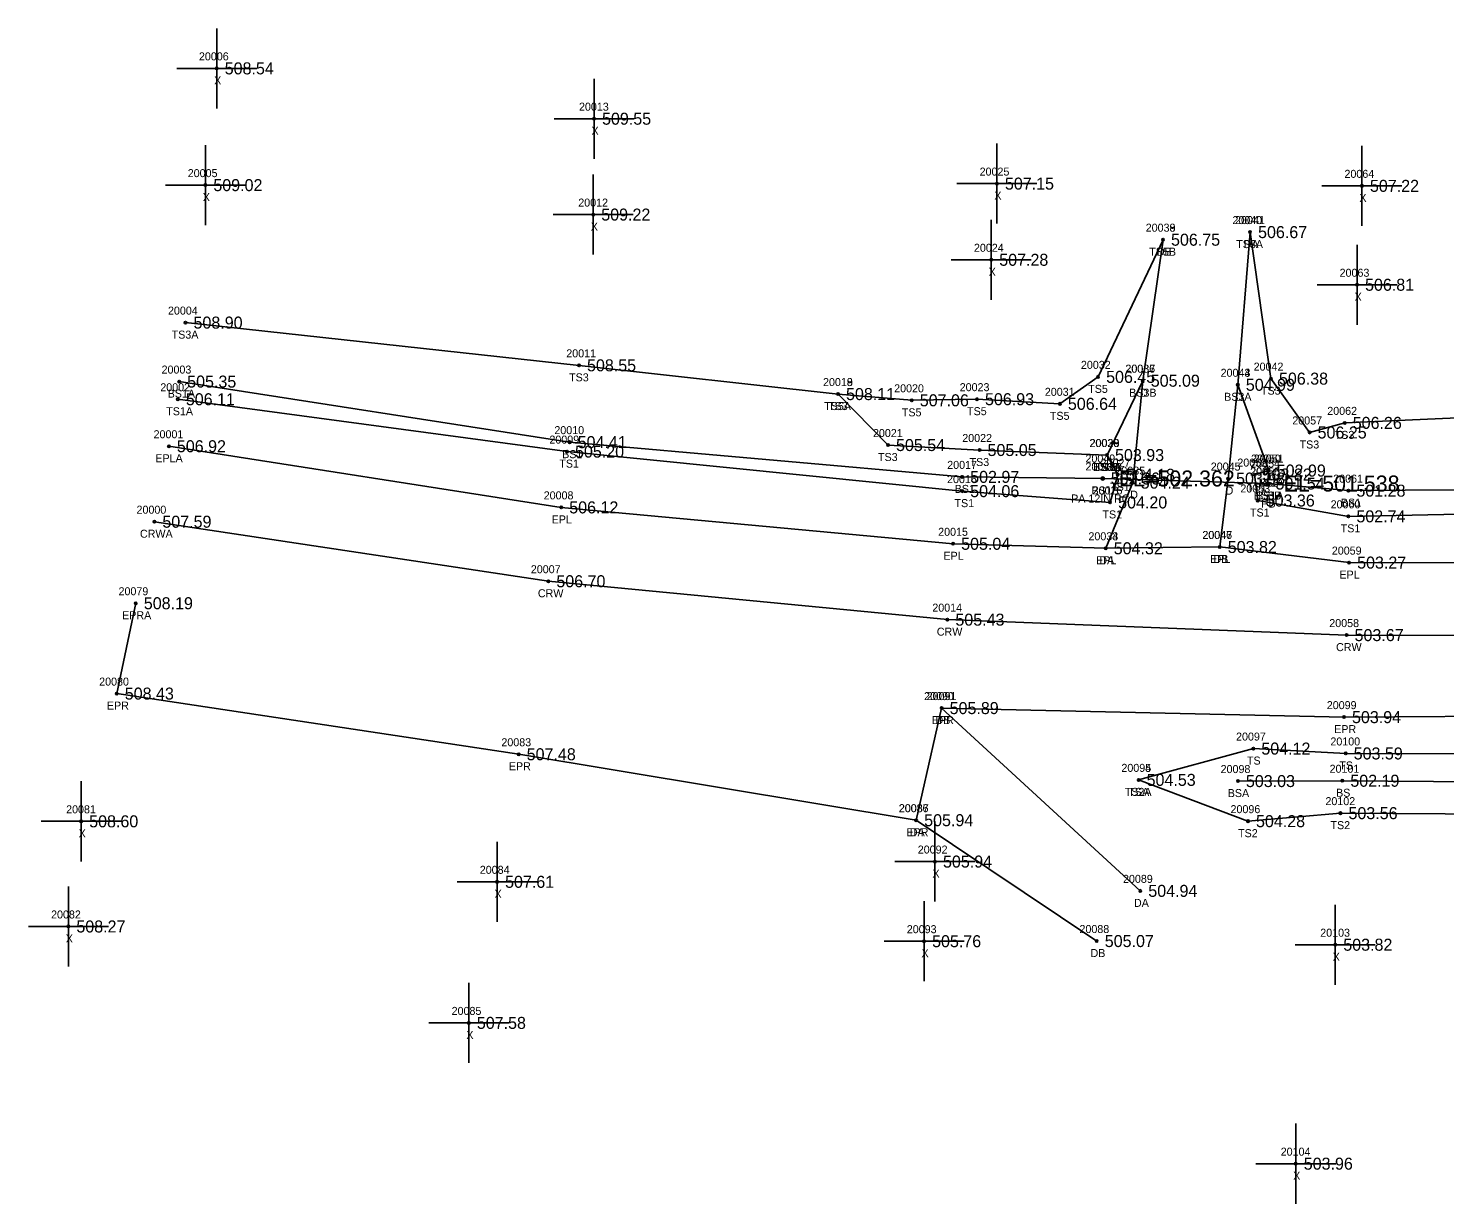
# Model space of a CAD drawing. Extents: x 1785066 to 1786589, y 770293 to 771312.
# Drawn here: x 1785066.3 to 1785243.3, y 770766.1 to 770912.9 of the extents above; entities that cross this region are included whole.
import ezdxf

# ---------------------------------------------------------------- set-up
doc = ezdxf.new("R2010")
doc.units = 0
for name, color, linetype in [('Default', 7, 'Continuous'), ('RD_DTM_BkLn1', 7, 'Continuous'), ('RD_DTM_BkLn2', 7, 'Continuous'), ('RD_DTM_BkLn_txCode', 7, 'Continuous'), ('RD_EX_DR_Pipe_txCode', 7, 'Continuous'), ('RD_EX_Driveway', 7, 'Continuous'), ('RD_EX_Driveway_txCode', 7, 'Continuous'), ('RD_EX_Misc', 7, 'Continuous'), ('RD_EX_Misc_txCode', 7, 'Continuous'), ('RD_EX_Road', 7, 'Continuous'), ('RD_EX_Road_txCode', 7, 'Continuous'), ('RD_EX_TX_Driveway_ELEV', 7, 'Continuous'), ('RD_EX_TX_Misc_ELEV', 7, 'Continuous'), ('RD_EX_TX_Road_ELEV', 7, 'Continuous'), ('RD_HC_Survey_ELEV', 7, 'Continuous'), ('RD_HC_Survey_txCode', 7, 'Continuous'), ('RD_SMD_Locator', 7, 'Continuous'), ('RD_TX_Pipe_ElevEX', 7, 'Continuous')]:
    doc.layers.add(name, color=color, linetype=linetype)

msp = doc.modelspace()

# ---------------------------------------------------------------- linework, layer by layer
at = {"layer": 'Default'}
msp.add_line((1785200.59, 770856.69), (1785221.18, 770856.06), dxfattribs=at)
at = {"layer": 'RD_DTM_BkLn1'}
msp.add_lwpolyline([(1785082.06, 770851.29), (1785131.3, 770843.85), (1785181.17, 770839.05), (1785231.06, 770837.12), (1785280.99, 770837.06), (1785330.97, 770838.45), (1785380.81, 770840.43), (1785480.56, 770843.94), (1785580.22, 770847.33), (1785679.99, 770850.66), (1785779.91, 770853.54)], dxfattribs=at)
at = {"layer": 'RD_DTM_BkLn2'}
msp.add_line((1785201.12, 770859.62), (1785205.59, 770868.91), dxfattribs=at)
for points in [[(1785219, 770887.48), (1785221.61, 770869.17), (1785226.44, 770862.44), (1785230.83, 770863.64), (1785281.61, 770865.88), (1785330.18, 770866.95), (1785380.62, 770873.53), (1785481.03, 770871.22), (1785579.17, 770869.06), (1785678.49, 770873.66), (1785753.25, 770880.69), (1785777.57, 770887.66), (1785796.72, 770894.6)], [(1785167.5, 770867.24), (1785176.72, 770866.46), (1785184.87, 770866.6), (1785195.23, 770866.02), (1785200.01, 770869.39), (1785208.12, 770886.53)], [(1785221.18, 770856.06), (1785231.29, 770855.17), (1785280.9, 770855.5), (1785330.48, 770855.32), (1785380.39, 770857.59), (1785481.4, 770861.59), (1785579.34, 770865.13), (1785679.06, 770868.59), (1785753.94, 770876.35), (1785778.96, 770883.81)], [(1785221.33, 770857.68), (1785219.57, 770857.18), (1785219.95, 770853.94), (1785231.29, 770851.96), (1785280.92, 770852.98), (1785330.39, 770854.04), (1785380.75, 770854.37), (1785480.88, 770858.51), (1785579.51, 770861.16), (1785679.28, 770865.65), (1785754.2, 770872.9), (1785779.7, 770881.19), (1785786.95, 770881.8), (1785789.14, 770878.77), (1785786.05, 770869.32), (1785786.11, 770839.44)], [(1785085.95, 770876.17), (1785135.13, 770870.83), (1785167.5, 770867.24), (1785173.75, 770860.87), (1785185.19, 770860.25), (1785201.12, 770859.62)], [(1785085.16, 770868.8), (1785133.96, 770861.23), (1785183.02, 770856.89), (1785200.59, 770856.69)], [(1785217.47, 770868.4), (1785221.33, 770857.68), (1785221.18, 770856.06)], [(1785084.99, 770866.59), (1785133.63, 770860.05), (1785183.02, 770855.11), (1785201.51, 770853.7), (1785202.47, 770857.15), (1785201.12, 770859.62)], [(1785205.07, 770819.03), (1785219.41, 770822.94), (1785230.95, 770822.33), (1785281.39, 770822.23), (1785331.37, 770822.34), (1785381.2, 770825.69), (1785481.76, 770828.75), (1785580.39, 770831.91), (1785680.81, 770834.37), (1785757.11, 770838.03), (1785775.28, 770836.8), (1785785.27, 770835.59), (1785786.11, 770839.44)], [(1785217.48, 770818.88), (1785230.53, 770818.92), (1785281.87, 770818.54), (1785331.33, 770820.31), (1785381.53, 770821.9), (1785481.77, 770825.03), (1785580.88, 770828.75), (1785679.45, 770830.28), (1785757.48, 770831.63), (1785774.02, 770829.34), (1785791.05, 770829.99), (1785795.95, 770830.77)], [(1785205.07, 770819.03), (1785218.74, 770813.87), (1785230.3, 770814.87), (1785282.58, 770814.55), (1785331.23, 770817.62), (1785381.61, 770819.76), (1785481.26, 770820.42), (1785579.63, 770825.21), (1785679.72, 770826.75), (1785756.33, 770825.6), (1785774.03, 770825.73), (1785791.3, 770827.72), (1785795.65, 770828.98)]]:
    msp.add_lwpolyline(points, dxfattribs=at)
at = {"layer": 'RD_EX_Driveway'}
for p, q in [((1785205.28, 770805.16), (1785180.45, 770828)), ((1785177.27, 770813.99), (1785199.84, 770798.89))]:
    msp.add_line(p, q, dxfattribs=at)
for points in [[(1785200.96, 770847.97), (1785204.33, 770856.17), (1785205.59, 770868.91), (1785208.12, 770886.53)], [(1785219, 770887.48), (1785217.47, 770868.4), (1785216.25, 770856.68), (1785215.21, 770848.13)]]:
    msp.add_lwpolyline(points, dxfattribs=at)
at = {"layer": 'RD_EX_Misc'}
for p, q in [((1785089.85, 770902.94), (1785089.85, 770912.94)), ((1785084.85, 770907.94), (1785094.85, 770907.94)), ((1785137.01, 770896.65), (1785137.01, 770906.65)), ((1785132.01, 770901.65), (1785142.01, 770901.65)), ((1785088.43, 770888.35), (1785088.43, 770898.35)), ((1785187.36, 770888.54), (1785187.36, 770898.54)), ((1785232.98, 770888.26), (1785232.98, 770898.26)), ((1785083.43, 770893.35), (1785093.43, 770893.35)), ((1785136.91, 770884.67), (1785136.91, 770894.67)), ((1785182.36, 770893.54), (1785192.36, 770893.54)), ((1785227.98, 770893.26), (1785237.98, 770893.26)), ((1785131.91, 770889.67), (1785141.91, 770889.67)), ((1785186.65, 770879.02), (1785186.65, 770889.02)), ((1785232.37, 770875.9), (1785232.37, 770885.9)), ((1785181.65, 770884.02), (1785191.65, 770884.02)), ((1785227.37, 770880.9), (1785237.37, 770880.9)), ((1785072.91, 770808.85), (1785072.91, 770818.85)), ((1785067.91, 770813.85), (1785077.91, 770813.85)), ((1785179.62, 770803.82), (1785179.62, 770813.82)), ((1785124.89, 770801.29), (1785124.89, 770811.29)), ((1785174.62, 770808.82), (1785184.62, 770808.82)), ((1785071.31, 770795.71), (1785071.31, 770805.71)), ((1785119.89, 770806.29), (1785129.89, 770806.29)), ((1785178.26, 770793.87), (1785178.26, 770803.87)), ((1785229.65, 770793.43), (1785229.65, 770803.43)), ((1785066.31, 770800.71), (1785076.31, 770800.71)), ((1785173.26, 770798.87), (1785183.26, 770798.87)), ((1785224.65, 770798.43), (1785234.65, 770798.43)), ((1785121.36, 770783.66), (1785121.36, 770793.66)), ((1785116.36, 770788.66), (1785126.36, 770788.66)), ((1785224.71, 770766.07), (1785224.71, 770776.07)), ((1785219.71, 770771.07), (1785229.71, 770771.07))]:
    msp.add_line(p, q, dxfattribs=at)
at = {"layer": 'RD_EX_Road'}
for points in [[(1785083.87, 770860.72), (1785132.91, 770853.08), (1785181.89, 770848.53), (1785200.96, 770847.97), (1785215.21, 770848.13), (1785231.38, 770846.18), (1785281.19, 770846.16), (1785330.68, 770847.27), (1785380.41, 770849.82), (1785480.96, 770852.71), (1785580.09, 770856.45), (1785680.2, 770859.84), (1785779.71, 770863.4)], [(1785079.74, 770841.1), (1785077.36, 770829.81), (1785127.59, 770822.23), (1785177.27, 770813.99), (1785180.45, 770828), (1785230.74, 770826.87), (1785281.16, 770827.18), (1785331.14, 770828.42), (1785381.03, 770830.27), (1785481.34, 770833.99), (1785580.1, 770837.94), (1785680.6, 770840.57), (1785780.28, 770843.87)]]:
    msp.add_lwpolyline(points, dxfattribs=at)
at = {"layer": 'RD_SMD_Locator'}
for centre, radius in [((1785089.85, 770907.94), 0.15), ((1785137.01, 770901.65), 0.15), ((1785088.43, 770893.35), 0.15), ((1785187.36, 770893.54), 0.15), ((1785232.98, 770893.26), 0.15), ((1785136.91, 770889.67), 0.15), ((1785208.12, 770886.53), 0.15), ((1785208.12, 770886.53), 0.15), ((1785219, 770887.48), 0.15), ((1785219, 770887.48), 0.15), ((1785186.65, 770884.02), 0.15), ((1785232.37, 770880.9), 0.15), ((1785085.95, 770876.17), 0.15), ((1785135.13, 770870.83), 0.15), ((1785085.16, 770868.8), 0.15), ((1785200.01, 770869.39), 0.15), ((1785205.59, 770868.91), 0.15), ((1785205.59, 770868.91), 0.15), ((1785217.47, 770868.4), 0.15), ((1785217.47, 770868.4), 0.15), ((1785221.61, 770869.17), 0.15), ((1785167.5, 770867.24), 0.15), ((1785167.5, 770867.24), 0.15), ((1785084.99, 770866.59), 0.15), ((1785176.72, 770866.46), 0.15), ((1785184.87, 770866.6), 0.15), ((1785195.23, 770866.02), 0.15), ((1785230.83, 770863.64), 0.15), ((1785226.44, 770862.44), 0.15), ((1785083.87, 770860.72), 0.15), ((1785133.63, 770860.05), 0.15), ((1785133.96, 770861.23), 0.15), ((1785173.75, 770860.87), 0.15), ((1785185.19, 770860.25), 0.15), ((1785201.12, 770859.62), 0.15), ((1785201.12, 770859.62), 0.15), ((1785201.12, 770859.62), 0.15), ((1785183.02, 770856.89), 0.15), ((1785200.59, 770856.69), 0.2), ((1785200.59, 770856.69), 0.15), ((1785202.47, 770857.15), 0.15), ((1785204.33, 770856.17), 0.15), ((1785216.25, 770856.68), 0.15), ((1785219.57, 770857.18), 0.15), ((1785221.18, 770856.06), 0.2), ((1785221.18, 770856.06), 0.15), ((1785221.18, 770856.06), 0.15), ((1785221.33, 770857.68), 0.15), ((1785221.33, 770857.68), 0.15), ((1785183.02, 770855.11), 0.15), ((1785231.29, 770855.17), 0.15), ((1785132.91, 770853.08), 0.15), ((1785201.51, 770853.7), 0.15), ((1785219.95, 770853.94), 0.15), ((1785082.06, 770851.29), 0.15), ((1785231.29, 770851.96), 0.15), ((1785181.89, 770848.53), 0.15), ((1785200.96, 770847.97), 0.15), ((1785200.96, 770847.97), 0.15), ((1785215.21, 770848.13), 0.15), ((1785215.21, 770848.13), 0.15), ((1785231.38, 770846.18), 0.15), ((1785131.3, 770843.85), 0.15), ((1785079.74, 770841.1), 0.15), ((1785181.17, 770839.05), 0.15), ((1785231.06, 770837.12), 0.15), ((1785077.36, 770829.81), 0.15), ((1785180.45, 770828), 0.15), ((1785180.45, 770828), 0.15), ((1785230.74, 770826.87), 0.15), ((1785219.41, 770822.94), 0.15), ((1785127.59, 770822.23), 0.15), ((1785230.95, 770822.33), 0.15), ((1785205.07, 770819.03), 0.15), ((1785205.07, 770819.03), 0.15), ((1785217.48, 770818.88), 0.15), ((1785230.53, 770818.92), 0.15), ((1785072.91, 770813.85), 0.15), ((1785177.27, 770813.99), 0.15), ((1785177.27, 770813.99), 0.15), ((1785218.74, 770813.87), 0.15), ((1785230.3, 770814.87), 0.15), ((1785179.62, 770808.82), 0.15), ((1785124.89, 770806.29), 0.15), ((1785205.28, 770805.16), 0.15), ((1785071.31, 770800.71), 0.15), ((1785178.26, 770798.87), 0.15), ((1785199.84, 770798.89), 0.15), ((1785229.65, 770798.43), 0.15), ((1785121.36, 770788.66), 0.15), ((1785224.71, 770771.07), 0.15)]:
    msp.add_circle(centre, radius, dxfattribs=at)

# ---------------------------------------------------------------- texts
at = {"layer": 'RD_DTM_BkLn_txCode'}
for s, p in [('20038', (1785205.96, 770887.53)), ('20041', (1785217.13, 770888.48)), ('TS3A', (1785217.27, 770885.48)), ('TS5B', (1785206.4, 770884.53)), ('20004', (1785083.76, 770877.17)), ('TS3A', (1785084.22, 770874.17)), ('20011', (1785133.54, 770871.83)), ('20003', (1785082.96, 770869.8)), ('20032', (1785197.86, 770870.39)), ('20037', (1785203.43, 770869.91)), ('20044', (1785215.32, 770869.4)), ('20042', (1785219.45, 770870.17)), ('20002', (1785082.8, 770867.59)), ('TS3', (1785133.89, 770868.83)), ('20018', (1785165.63, 770868.24)), ('20019', (1785165.63, 770868.24)), ('20023', (1785182.71, 770867.6)), ('BS1A', (1785083.72, 770866.8)), ('20020', (1785174.52, 770867.46)), ('20031', (1785193.35, 770867.02)), ('TS5', (1785198.77, 770867.39)), ('BS3B', (1785203.89, 770866.91)), ('BS3A', (1785215.76, 770866.4)), ('TS3', (1785220.36, 770867.17)), ('TS1A', (1785083.54, 770864.59)), ('TS5A', (1785165.77, 770865.24)), ('TS3', (1785166.26, 770865.24)), ('TS5', (1785175.48, 770864.46)), ('TS5', (1785183.63, 770864.6)), ('TS5', (1785193.98, 770864.02)), ('20062', (1785228.65, 770864.64)), ('20010', (1785132.05, 770862.23)), ('20057', (1785224.28, 770863.44)), ('20009', (1785131.43, 770861.05)), ('20021', (1785171.87, 770861.87)), ('20022', (1785183.03, 770861.25)), ('20030', (1785198.92, 770860.62)), ('20028', (1785198.96, 770860.62)), ('20029', (1785198.96, 770860.62)), ('TS3', (1785225.19, 770860.44)), ('TS3', (1785229.58, 770861.64)), ('BS1', (1785133.02, 770859.23)), ('TS3', (1785172.5, 770858.87)), ('20050', (1785219.13, 770858.68)), ('20051', (1785219.46, 770858.68)), ('TS1', (1785132.67, 770858.05)), ('20017', (1785181.15, 770857.89)), ('TS3', (1785183.94, 770858.25)), ('20048', (1785198.43, 770857.69)), ('TS3B', (1785199.4, 770857.62)), ('BS3A', (1785199.4, 770857.62)), ('TS1B', (1785199.68, 770857.62)), ('20027', (1785200.32, 770858.15)), ('20052', (1785217.41, 770858.18)), ('20056', (1785219, 770857.06)), ('20055', (1785219.03, 770857.06)), ('20016', (1785181.13, 770856.11)), ('TS1', (1785201.51, 770855.15)), ('TS1', (1785218.61, 770855.18)), ('TS1A', (1785219.88, 770855.68)), ('BS3', (1785220.1, 770855.68)), ('20061', (1785229.39, 770856.17)), ('BS1', (1785182.08, 770854.89)), ('BS1B', (1785199.17, 770854.69)), ('20026', (1785199.33, 770854.7)), ('20053', (1785217.79, 770854.94)), ('BS3B', (1785219.48, 770854.06)), ('BS1A', (1785219.75, 770854.06)), ('TS1', (1785182.06, 770853.11)), ('TS1', (1785200.55, 770851.7)), ('TS1', (1785218.99, 770851.94)), ('20060', (1785229.07, 770852.96)), ('BS1', (1785230.35, 770853.17)), ('TS1', (1785230.33, 770849.96)), ('20097', (1785217.25, 770823.94)), ('20100', (1785229.04, 770823.33)), ('20094', (1785202.92, 770820.03)), ('20095', (1785202.92, 770820.03)), ('20098', (1785215.32, 770819.88)), ('TS', (1785218.61, 770820.94)), ('20101', (1785228.94, 770819.92)), ('TS', (1785230.15, 770820.33)), ('TS2A', (1785203.34, 770817.03)), ('TSA', (1785203.79, 770817.03)), ('BSA', (1785216.21, 770816.88)), ('BS', (1785229.75, 770816.92)), ('20096', (1785216.56, 770814.87)), ('20102', (1785228.42, 770815.87)), ('TS2', (1785229.05, 770812.87)), ('TS2', (1785217.5, 770811.87))]:
    msp.add_text(s, height=1, dxfattribs=at).set_placement(p)
at = {"layer": 'RD_EX_DR_Pipe_txCode'}
for s, p in [('20049', (1785198.43, 770858.69)), ('20054', (1785219.03, 770858.06)), ('PA 12IN RC', (1785196.64, 770853.69)), ('PB', (1785220.4, 770853.06))]:
    msp.add_text(s, height=1, dxfattribs=at).set_placement(p)
at = {"layer": 'RD_EX_Driveway_txCode'}
for s, p in [('20039', (1785205.96, 770887.53)), ('20040', (1785216.8, 770888.48)), ('DA', (1785218.21, 770885.48)), ('DB', (1785207.34, 770884.53)), ('20036', (1785203.41, 770869.91)), ('20043', (1785215.32, 770869.4)), ('D', (1785205.28, 770866.91)), ('D', (1785217.17, 770866.4)), ('20035', (1785202.17, 770857.17)), ('20045', (1785214.09, 770857.68)), ('D', (1785204.02, 770854.17)), ('D', (1785215.94, 770854.68)), ('20034', (1785198.8, 770848.97)), ('20047', (1785213.05, 770849.13)), ('DA', (1785200.16, 770845.97)), ('DB', (1785214.43, 770846.13)), ('20090', (1785178.26, 770829)), ('DB', (1785179.68, 770826)), ('20087', (1785175.12, 770814.99)), ('DA', (1785176.48, 770811.99)), ('20089', (1785203.12, 770806.16)), ('DA', (1785204.49, 770803.16)), ('20088', (1785197.68, 770799.89)), ('DB', (1785199.06, 770796.89))]:
    msp.add_text(s, height=1, dxfattribs=at).set_placement(p)
at = {"layer": 'RD_EX_Misc_txCode'}
for s, p in [('20006', (1785087.63, 770908.94)), ('X', (1785089.53, 770905.94)), ('20013', (1785135.13, 770902.65)), ('X', (1785136.69, 770899.65)), ('20005', (1785086.23, 770894.35)), ('20025', (1785185.2, 770894.54)), ('20064', (1785230.8, 770894.26)), ('X', (1785088.11, 770891.35)), ('20012', (1785135.04, 770890.67)), ('X', (1785187.04, 770891.54)), ('X', (1785232.66, 770891.26)), ('X', (1785136.6, 770887.67)), ('20024', (1785184.49, 770885.02)), ('X', (1785186.33, 770882.02)), ('20063', (1785230.19, 770881.9)), ('X', (1785232.06, 770878.9)), ('20081', (1785071.03, 770814.85)), ('X', (1785072.59, 770811.85)), ('20092', (1785177.47, 770809.82)), ('20084', (1785122.73, 770807.29)), ('X', (1785179.31, 770806.82)), ('X', (1785124.57, 770804.29)), ('20082', (1785069.15, 770801.71)), ('X', (1785070.99, 770798.71)), ('20093', (1785176.1, 770799.87)), ('20103', (1785227.77, 770799.43)), ('X', (1785177.94, 770796.87)), ('X', (1785229.33, 770796.43)), ('20085', (1785119.21, 770789.66)), ('X', (1785121.05, 770786.66)), ('20104', (1785222.83, 770772.07)), ('X', (1785224.39, 770769.07))]:
    msp.add_text(s, height=1, dxfattribs=at).set_placement(p)
at = {"layer": 'RD_EX_Road_txCode'}
for s, p in [('20001', (1785081.96, 770861.72)), ('EPLA', (1785082.18, 770858.72)), ('20008', (1785130.72, 770854.08)), ('EPL', (1785131.71, 770851.08)), ('20015', (1785180.02, 770849.53)), ('20033', (1785198.8, 770848.97)), ('20046', (1785213.03, 770849.13)), ('EPL', (1785180.68, 770846.53)), ('20059', (1785229.22, 770847.18)), ('EPL', (1785199.75, 770845.97)), ('EPL', (1785214, 770846.13)), ('EPL', (1785230.17, 770844.18)), ('20079', (1785077.58, 770842.1)), ('EPRA', (1785078.03, 770839.1)), ('20080', (1785075.16, 770830.81)), ('20091', (1785178.58, 770829)), ('EPR', (1785076.13, 770827.81)), ('20099', (1785228.59, 770827.87)), ('EPR', (1785179.23, 770826)), ('EPR', (1785229.51, 770824.87)), ('20083', (1785125.43, 770823.23)), ('EPR', (1785126.36, 770820.23)), ('20086', (1785175.09, 770814.99)), ('EPR', (1785176.05, 770811.99))]:
    msp.add_text(s, height=1, dxfattribs=at).set_placement(p)
at = {"layer": 'RD_EX_TX_Driveway_ELEV'}
for s, p in [('506.67', (1785220, 770886.73)), ('506.75', (1785209.12, 770885.78)), ('505.09', (1785206.59, 770868.16)), ('504.99', (1785218.47, 770867.65)), ('504.24', (1785205.33, 770855.42)), ('503.98', (1785217.25, 770855.93)), ('504.32', (1785201.96, 770847.22)), ('503.82', (1785216.21, 770847.38)), ('505.89', (1785181.45, 770827.25)), ('505.94', (1785178.27, 770813.24)), ('504.94', (1785206.28, 770804.41)), ('505.07', (1785200.84, 770798.14))]:
    msp.add_text(s, height=1.5, dxfattribs=at).set_placement(p)
at = {"layer": 'RD_EX_TX_Misc_ELEV'}
for s, p in [('508.54', (1785090.85, 770907.19)), ('509.55', (1785138.01, 770900.9)), ('509.02', (1785089.43, 770892.6)), ('507.15', (1785188.36, 770892.79)), ('507.22', (1785233.98, 770892.51)), ('509.22', (1785137.91, 770888.92)), ('506.67', (1785220, 770886.73)), ('506.75', (1785209.12, 770885.78)), ('507.28', (1785187.65, 770883.27)), ('506.81', (1785233.37, 770880.15)), ('508.90', (1785086.95, 770875.42)), ('508.55', (1785136.13, 770870.08)), ('505.35', (1785086.16, 770868.05)), ('506.45', (1785201.01, 770868.64)), ('505.09', (1785206.59, 770868.16)), ('504.99', (1785218.47, 770867.65)), ('506.38', (1785222.61, 770868.42)), ('506.11', (1785085.99, 770865.84)), ('508.11', (1785168.5, 770866.49)), ('508.11', (1785168.5, 770866.49)), ('507.06', (1785177.72, 770865.71)), ('506.93', (1785185.87, 770865.85)), ('506.64', (1785196.23, 770865.27)), ('506.25', (1785227.44, 770861.69)), ('506.26', (1785231.83, 770862.89)), ('504.41', (1785134.96, 770860.48)), ('505.54', (1785174.75, 770860.12)), ('505.20', (1785134.63, 770859.3)), ('505.05', (1785186.19, 770859.5)), ('503.93', (1785202.12, 770858.87)), ('503.93', (1785202.12, 770858.87)), ('503.93', (1785202.12, 770858.87)), ('504.18', (1785203.47, 770856.4)), ('503.82', (1785220.57, 770856.43)), ('502.99', (1785222.33, 770856.93)), ('502.99', (1785222.33, 770856.93)), ('502.97', (1785184.02, 770856.14)), ('502.36', (1785201.59, 770855.94)), ('501.54', (1785222.18, 770855.31)), ('501.54', (1785222.18, 770855.31)), ('504.06', (1785184.02, 770854.36)), ('504.20', (1785202.51, 770852.95)), ('503.36', (1785220.95, 770853.19)), ('501.28', (1785232.29, 770854.42)), ('502.74', (1785232.29, 770851.21)), ('504.12', (1785220.41, 770822.19)), ('503.59', (1785231.95, 770821.58)), ('504.53', (1785206.07, 770818.28)), ('504.53', (1785206.07, 770818.28)), ('503.03', (1785218.48, 770818.13)), ('502.19', (1785231.53, 770818.17)), ('503.56', (1785231.3, 770814.12)), ('508.60', (1785073.91, 770813.1)), ('504.28', (1785219.74, 770813.12)), ('505.94', (1785180.62, 770808.07)), ('507.61', (1785125.89, 770805.54)), ('508.27', (1785072.31, 770799.96)), ('505.76', (1785179.26, 770798.12)), ('503.82', (1785230.65, 770797.68)), ('507.58', (1785122.36, 770787.91)), ('503.96', (1785225.71, 770770.32))]:
    msp.add_text(s, height=1.5, dxfattribs=at).set_placement(p)
at = {"layer": 'RD_EX_TX_Road_ELEV'}
for s, p in [('506.92', (1785084.87, 770859.97)), ('506.12', (1785133.91, 770852.33)), ('505.04', (1785182.89, 770847.78)), ('504.32', (1785201.96, 770847.22)), ('503.82', (1785216.21, 770847.38)), ('503.27', (1785232.38, 770845.43)), ('508.19', (1785080.74, 770840.35)), ('508.43', (1785078.36, 770829.06)), ('505.89', (1785181.45, 770827.25)), ('503.94', (1785231.74, 770826.12)), ('507.48', (1785128.59, 770821.48)), ('505.94', (1785178.27, 770813.24))]:
    msp.add_text(s, height=1.5, dxfattribs=at).set_placement(p)
at = {"layer": 'RD_HC_Survey_ELEV'}
for s, p in [('507.59', (1785083.06, 770850.54)), ('506.70', (1785132.3, 770843.1)), ('505.43', (1785182.17, 770838.3)), ('503.67', (1785232.06, 770836.37))]:
    msp.add_text(s, height=1.5, dxfattribs=at).set_placement(p)
at = {"layer": 'RD_HC_Survey_txCode'}
for s, p in [('20000', (1785079.83, 770852.29)), ('CRWA', (1785080.26, 770849.29)), ('20007', (1785129.11, 770844.85)), ('CRW', (1785129.99, 770841.85)), ('20014', (1785179.29, 770840.05)), ('20058', (1785228.9, 770838.12)), ('CRW', (1785179.85, 770837.05)), ('CRW', (1785229.75, 770835.12))]:
    msp.add_text(s, height=1, dxfattribs=at).set_placement(p)
at = {"layer": 'RD_TX_Pipe_ElevEX'}
for s, p in [('EL=502.362', (1785202.59, 770855.69)), ('EL=501.538', (1785223.18, 770855.06))]:
    msp.add_text(s, height=2, dxfattribs=at).set_placement(p)

doc.saveas('drawing.dxf')
